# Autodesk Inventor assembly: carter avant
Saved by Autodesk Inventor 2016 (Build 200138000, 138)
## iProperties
Created: 2013-10
Part Number: carter avant
Material: Générique
Document SubType Name: Assembly
Designer: Bruno
Author: Bruno
Sending System: SolidWorks 2013
Last Author: christophe
Last Saved: 2014-02-15
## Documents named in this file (7)
- D:\Cours\Systèmes SI\Robot Haptique\Documentations_pedagogique\Modèle solidworks\Réel\carter avant.iam
- D:\Cours\Systèmes SI\Robot Haptique\Documentations_pedagogique\Modèle solidworks\Réel\carter avant01.ipt
- D:\Cours\Systèmes SI\Robot Haptique\Documentations_pedagogique\Modèle solidworks\Réel\carter avant1.ipt
- D:\Cours\Systèmes SI\Robot Haptique\Documentations_pedagogique\Modèle solidworks\Réel\CARTER NEZ.ipt
- D:\Cours\Systèmes SI\Robot Haptique\Documentations_pedagogique\Modèle solidworks\Réel\carter avant02.ipt
- D:\Cours\Systèmes SI\Robot Haptique\Documentations_pedagogique\Modèle solidworks\Réel\carter avant03.ipt
- D:\Cours\Systèmes SI\Robot Haptique\Documentations_pedagogique\Modèle solidworks\Réel\Vis à tôle tête cylindrique cruciforme H 2,9x13 - C.ipt
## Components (8 placed, 6 different names)
1. carter avant01:1
2. carter avant1:1
3. CARTER NEZ:1
4. carter avant02:1
5. carter avant03:1
6. Vis à tôle tête cylindrique cruciforme H 2,9x13 - C:1
7. Vis à tôle tête cylindrique cruciforme H 2,9x13 - C:2
8. Vis à tôle tête cylindrique cruciforme H 2,9x13 - C:3
